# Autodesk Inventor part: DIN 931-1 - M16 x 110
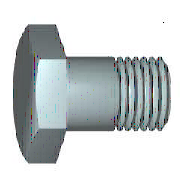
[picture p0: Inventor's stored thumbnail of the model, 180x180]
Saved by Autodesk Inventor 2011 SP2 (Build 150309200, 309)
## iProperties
Created: 2010-02
Part Number: DIN 931-1 - M16 x 110
Material: Stahl, weich, unlegiert
Description: Sechskantschraube
Document SubType Name: Modeling
Standard: DIN 931-1
Designer: JRE
Standard Revision: 2001
Standards Organization: DIN
Language: de-DE
Size Designation: M16 x 110
Categories: <MemberInstance><Categories><Category DisplayName="Verbindungselemente" InternalName="e4da775c-781d-43d5-af7c-5136215cf5a6" Mnemonic="FSTN"><Category DisplayNam
Density: 1 g/cm^3
IsCustomPart: 0
Author: JRE
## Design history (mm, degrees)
body "Solid1"
workplane "Work Plane1"
revolve "Körper" stored, may be unused: angle "d12" = 90 deg
sketch "Skizze2"
  geometry: L1 (0, 13.856)-(12, 6.928); L2 (12, 6.928)-(12, -6.928); L3 (12, -6.928)-(0, -13.856); L4 (0, -13.856)-(-12, -6.928); L5 (-12, -6.928)-(-12, 6.928); L6 (-12, 6.928)-(0, 13.856); 2 further points
  constraints: 12 end point, 1 coincident, 1 vertical, 11 other
  dimensions: "d11" = 24 distance between parallel lines of L5 L2 (= SW)
extrude "Kopf" join sketch "Skizze2" distance "d3" = 9.2 (= KOH - SD); taper "d4" = 0 deg
revolve "Fase1" stored, may be unused: angle "d21" = 90 deg
feature "Gewinde" dims "d15" = 38 (= GEL), "d16" = 0
chamfer "Fase2" distance "d6" = 1.2269 (= -0.5 x SPD + 0.5 x GD); stored, may be unused: second distance "d7" = 1.227 (computed from GUL), angle "d55" = 45 deg
sketch "Skizze1"
  geometry: L1 (0, 11.25)-(0, 8); L2 (72, 8)-(110, 8); L3 (110, 8)-(110, 0); L4 (110, 0)-(-0.8, 0); L5 (-22.96, 0)-(132.16, 0) reference; L6 (-0.8, 0)-(-0.8, 11.25); L7 (-0.8, 11.25)-(0, 11.25); L8 (72, 8)-(70.773, 8); L9 (70.773, 8)-(0, 8); L10 (0, -2.25)-(0, 13.5) reference
  constraints: 16 end point, 2 collinear, 2 perpendicular, 1 parallel
  dimensions: "d0" = 110 distance between parallel lines of L3 L1 (= NLG); "d1" = 38 distance from line of L2.start L3 (= GEL); "d2" = 16 diameter of L2 L4 (= GD); "d9" = 0.8001 distance between parallel lines of L6 L1 (computed from SD); "d10" = 22.5 diameter of L7 L4 (= SD2); "d13" = 1.227 distance of L2.start L8.end (computed from GAL); "d14" = 16 diameter of L9 L4 (= BDM)
sketch "Skizze4"
  geometry: L1 (-10, 12)-(-10, 13.856); L2 (-10, 13.856)-(-8.928, 13.856); L3 (-8.928, 13.856)-(-10, 12); L4 (-11.84, 0)-(1.04, 0) reference; L5 (-0.8, 13.856)-(-10, 13.856) reference; L6 (-10, 6.928)-(-10, 13.856) reference
  constraints: 6 end point, 2 collinear, 1 perpendicular, 1 vertical
  dimensions: "d5" = 30 deg angle of L3 L1 (= ANG1); "d19" = 24 diameter of L1.start L4 (= SW0)
other parameters: "NLG" = 110 [user parameter; used in 1 equation term], "GD" = 16 (= NND) [user parameter; used in 2 equation terms], "BDM" = 16 (= NND) [user parameter; used in 1 equation term], "KOH" = 10 [user parameter; used in 1 equation term], "GEL" = 38 [user parameter; used in 2 equation terms], "SW" = 24 [user parameter; used in 3 equation terms], "SW0" = 24 (= SW) [user parameter; used in 1 equation term], "SPD" = 13.5462 (= NND - 1.2269 x PTC) [user parameter; used in 1 equation term], "SD2" = 22.5 [user parameter; used in 1 equation term], "SD" = 0.8 [user parameter; used in 2 equation terms], "ANG1" = 30 deg [user parameter; used in 1 equation term], "GAL" = 1.2269 (= 0.61345 x PTC) [user parameter; used in 1 equation term], "GUL" = 1.2269 (= 0.61345 x PTC) [user parameter; used in 1 equation term], "d8" = 0, "RR" = 0.6 [user parameter], "d57" = 0, "d58" = 0, "TPU" = 5 (computed from PTC) [user parameter], "GD1" = 13.5462 (= THREADDIA - 1.2269 x PTC) [user parameter], "THREADDIA" = 16 [user parameter; used in 1 equation term], "TOA" = 30 deg [user parameter], "PTC" = 2 [user parameter; used in 5 equation terms], "NND" = 16 [user parameter; used in 3 equation terms], "E0" = 27.72 (= 1.155 x SW) [user parameter]
